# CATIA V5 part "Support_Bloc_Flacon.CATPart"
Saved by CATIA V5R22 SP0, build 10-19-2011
Part number: Support_Bloc_Flacon
Bounding box of the stored display mesh (mm): x -193.5 to 193.5, y -31 to 31, z 0 to 5
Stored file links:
  U:\S9A\PER\CAO\Assemblage\Reservoir_Flacon\Sous_Ensemble_Flacon\Support_Bloc_Flacon.CATPart
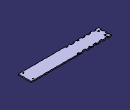
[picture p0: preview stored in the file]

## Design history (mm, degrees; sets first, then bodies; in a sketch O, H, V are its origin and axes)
Body1 (main body)
  Sketch1 on xy-plane, origin (0, 0, 0), H (1, 0, 0), V (0, 1, 0)
    point P1 (-193.5, 31)
    line L1 (-193.5, 31) -> (193.5, 31)
    line L2 (193.5, 31) -> (193.5, -31)
    line L3 (193.5, -31) -> (-193.5, -31)
    line L4 (-193.5, -31) -> (-193.5, 31)
    point P2 (193.5, 31)
    point P3 (193.5, -31)
    point P4 (-193.5, -31)
    length L4 = 62
    length L1 = 387
    horizontal: L1 H, L3 H
    vertical: L2 V, L4 V
    equidistance: P3 P1 O, P2 P4 O
  Pad1: profile Sketch1, direction (0, 0, 1), length 5
  Sketch2 on end face of Pad1, origin (0, 0, 5), H (1, 0, 0), V (0, 1, 0)
    point P1 (-40.5, -31)
    line L1 (-40.5, -31) -> (-32.5, -31)
    line L2 (-32.5, -31) -> (-32.5, -26)
    line L3 (-32.5, -26) -> (-40.5, -26)
    line L4 (-40.5, -26) -> (-40.5, -31)
    point P2 (-32.5, -31)
    point P3 (-32.5, -26)
    point P4 (-40.5, -26)
    reference projected line E1 (193.5, -31) -> (193.5, 31) from edge [face of Pad1 from Sketch1.L2 | end face of Pad1]
    reference projected line E2 (-193.5, -31) -> (193.5, -31) from edge [face of Pad1 from Sketch1.L3 | end face of Pad1]
    point P5 (-55.5, -31)
    line L5 (-55.5, -31) -> (-71.5, -31)
    line L6 (-71.5, -31) -> (-71.5, -26)
    line L7 (-71.5, -26) -> (-55.5, -26)
    line L8 (-55.5, -26) -> (-55.5, -31)
    point P6 (-71.5, -31)
    point P7 (-71.5, -26)
    point P8 (-55.5, -26)
    point P9 (-86.5, -31)
    line L9 (-86.5, -31) -> (-94.5, -31)
    line L10 (-94.5, -31) -> (-94.5, -26)
    line L11 (-94.5, -26) -> (-86.5, -26)
    line L12 (-86.5, -26) -> (-86.5, -31)
    point P10 (-94.5, -31)
    point P11 (-94.5, -26)
    point P12 (-86.5, -26)
    point P13 (-40.5, 31)
    point P14 (-32.5, 31)
    point P15 (-32.5, 26)
    point P16 (-40.5, 26)
    point P17 (-55.5, 31)
    point P18 (-71.5, 31)
    point P19 (-71.5, 26)
    point P20 (-55.5, 26)
    point P21 (-86.5, 31)
    point P22 (-94.5, 31)
    point P23 (-94.5, 26)
    point P24 (-86.5, 26)
    line L13 (-40.5, 31) -> (-32.5, 31)
    line L14 (-32.5, 31) -> (-32.5, 26)
    line L15 (-32.5, 26) -> (-40.5, 26)
    line L16 (-40.5, 26) -> (-40.5, 31)
    line L17 (-55.5, 31) -> (-71.5, 31)
    line L18 (-71.5, 31) -> (-71.5, 26)
    line L19 (-71.5, 26) -> (-55.5, 26)
    line L20 (-55.5, 26) -> (-55.5, 31)
    line L21 (-86.5, 31) -> (-94.5, 31)
    line L22 (-94.5, 31) -> (-94.5, 26)
    line L23 (-94.5, 26) -> (-86.5, 26)
    line L24 (-86.5, 26) -> (-86.5, 31)
    distance L2 E1 = 226
    length L3 = 8
    length L4 = 5
    distance L8 L4 = 15
    length L7 = 16
    length L11 = 8
    distance L12 L6 = 15
    horizontal: L1 H, L3 H, L5 H, L7 H, L9 H, L11 H
    vertical: L2 V, L4 V, L6 V, L8 V, L10 V, L12 V
    coincidence: L1 E2, P5 L1, L3 L7, P9 L1, L7 L11
    symmetry: P1 P13 H, P2 P14 H, P3 P15 H, P4 P16 H, P5 P17 H, P6 P18 H, P7 P19 H, P8 P20 H, P9 P21 H, P10 P22 H, P11 P23 H, P12 P24 H, L1 L13 H, L2 L14 H, L3 L15 H, L4 L16 H, L5 L17 H, L6 L18 H, L7 L19 H, L8 L20 H, L9 L21 H, L10 L22 H, L11 L23 H, L12 L24 H
  Pocket1: profile Sketch2, direction (0, 0, -1), through (limit type 6)
  Sketch3 on end face of Pad1, origin (0, 0, 5), H (1, 0, 0), V (0, 1, 0)
    point P1 (-109.5, -31)
    line L1 (-109.5, -31) -> (-122.5, -31)
    line L2 (-122.5, -31) -> (-122.5, -26)
    line L3 (-122.5, -26) -> (-109.5, -26)
    line L4 (-109.5, -26) -> (-109.5, -31)
    point P2 (-122.5, -31)
    point P3 (-122.5, -26)
    point P4 (-109.5, -26)
    reference projected line E1 (-193.5, -31) -> (193.5, -31) from edge [face of Pad1 from Sketch1.L3 | end face of Pad1]
    reference projected line E2 (-94.5, -26) -> (-94.5, -31) from edge [end face of Pad1 | face of Pocket1 from Sketch2.L10]
    point P5 (-109.5, 31)
    point P6 (-122.5, 31)
    point P7 (-122.5, 26)
    point P8 (-109.5, 26)
    line L5 (-109.5, 31) -> (-122.5, 31)
    line L6 (-122.5, 31) -> (-122.5, 26)
    line L7 (-122.5, 26) -> (-109.5, 26)
    line L8 (-109.5, 26) -> (-109.5, 31)
    distance L4 E2 = 15
    length L3 = 13
    length L2 = 5
    horizontal: L1 H, L3 H
    vertical: L2 V, L4 V
    coincidence: L1 E1
    symmetry: P1 P5 H, P2 P6 H, P3 P7 H, P4 P8 H, L1 L5 H, L2 L6 H, L3 L7 H, L4 L8 H
  Pocket2: profile Sketch3, direction (0, 0, -1), through (limit type 6)
  RectPattern1: of Pocket2, direction 1 instances 3, spacing 28, along end face of Pad1 reversed
  Sketch4 on end face of Pad1, origin (0, 0, 5), H (1, 0, 0), V (0, 1, 0)
    point P1 (-193.5, 19)
    line L1 (-193.5, 19) -> (-188.5, 19)
    line L2 (-188.5, 19) -> (-188.5, 6)
    line L3 (-188.5, 6) -> (-193.5, 6)
    line L4 (-193.5, 6) -> (-193.5, 19)
    point P2 (-188.5, 19)
    point P3 (-188.5, 6)
    point P4 (-193.5, 6)
    reference projected line E1 (-193.5, 31) -> (-193.5, -31) from edge [face of Pad1 from Sketch1.L4 | end face of Pad1]
    reference projected line E2 (193.5, 31) -> (-193.5, 31) from edge [face of Pad1 from Sketch1.L1 | end face of Pad1]
    point P5 (-193.5, -19)
    point P6 (-188.5, -19)
    point P7 (-188.5, -6)
    point P8 (-193.5, -6)
    line L5 (-193.5, -19) -> (-188.5, -19)
    line L6 (-188.5, -19) -> (-188.5, -6)
    line L7 (-188.5, -6) -> (-193.5, -6)
    line L8 (-193.5, -6) -> (-193.5, -19)
    length L1 = 5
    length L2 = 13
    distance L1 E2 = 12
    horizontal: L1 H, L3 H
    vertical: L2 V, L4 V
    coincidence: L4 E1
    symmetry: P1 P5 H, P2 P6 H, P3 P7 H, P4 P8 H, L1 L5 H, L2 L6 H, L3 L7 H, L4 L8 H
  Pocket3: profile Sketch4, direction (0, 0, -1), through (limit type 6)
  Sketch5 on end face of Pad1, origin (-164.3773, -4.1902, 5), H (1, 0, 0), V (0, 1, 0)
    point P1 (-14.1227, -11.8098)
    reference projected line E1 (-29.1227, 35.1902) -> (-29.1227, -26.8098) from edge [face of Pad1 from Sketch1.L4 | end face of Pad1]
    reference projected line E2 (-29.1227, -26.8098) -> (357.8773, -26.8098) from edge [face of Pad1 from Sketch1.L3 | end face of Pad1]
    distance P1 E1 = 15
    distance P1 E2 = 15
  Hole1: placed by Sketch5, at (-178.5, -16, 5) direction (0, 0, -1), diameter 5, through (limit type 6), countersink depth 3, countersink angle 90
  Mirror1: of Hole1, about zx-plane
  Sketch6 on end face of Pad1, origin (163.4997, -7.5185, 5), H (1, 0, 0), V (0, 1, 0)
    point P1 (14.5003, -15.9815)
    reference projected line E1 (30.0003, -23.4815) -> (30.0003, 38.5185) from edge [face of Pad1 from Sketch1.L2 | end face of Pad1]
    reference projected line E2 (-356.9997, -23.4815) -> (30.0003, -23.4815) from edge [face of Pad1 from Sketch1.L3 | end face of Pad1]
    distance P1 E1 = 15.5
    distance P1 E2 = 7.5
  Hole2: placed by Sketch6, at (178, -23.5, 5) direction (0, 0, -1), diameter 5, through (limit type 6)
  Mirror2: of Hole2, about zx-plane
